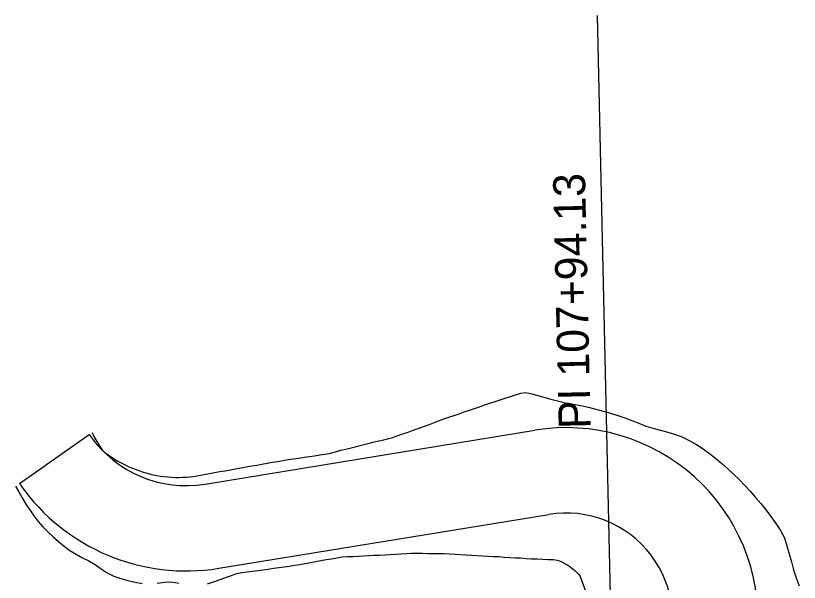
# Model space of a CAD drawing. Extents: x 834421 to 837111, y 495679 to 497078.
# Drawn here: x 835442.1 to 835588.9, y 496971.3 to 497077.5 of the extents above; entities that cross this region are included whole.
import ezdxf

# ---------------------------------------------------------------- set-up
doc = ezdxf.new("R2010")
doc.units = 0
for name, color, linetype in [('R_Horz Alg Annot', 7, 'Continuous'), ('R_Proposed Const Limits', 7, 'Continuous'), ('R_Proposed Road', 7, 'Continuous')]:
    doc.layers.add(name, color=color, linetype=linetype)

msp = doc.modelspace()

# ---------------------------------------------------------------- linework, layer by layer
at = {"layer": 'R_Horz Alg Annot'}
msp.add_lwpolyline([(835553.82, 496957.58), (835551.11, 497077.55)], dxfattribs=at)
at = {"layer": 'R_Proposed Const Limits'}
for points in [[(835458.28, 496996.14), (835458.82, 496995.66), (835459.42, 496995.22), (835460.02, 496994.81), (835460.63, 496994.41), (835461.25, 496994.04), (835461.89, 496993.69), (835462.52, 496993.36), (835463.17, 496993.04), (835463.82, 496992.75), (835464.48, 496992.49), (835465.15, 496992.24), (835465.82, 496992.02), (835466.5, 496991.81), (835467.17, 496991.63), (835467.86, 496991.47), (835468.54, 496991.33), (835469.23, 496991.22), (835469.91, 496991.12), (835470.6, 496991.05), (835471.29, 496991), (835471.98, 496990.98), (835472.67, 496990.97), (835473.35, 496990.99), (835474.03, 496991.02), (835474.71, 496991.08), (835475.39, 496991.17), (835476.06, 496991.27), (835476.72, 496991.39), (835477.41, 496991.54), (835478.4, 496991.71), (835479.38, 496991.89), (835480.37, 496992.06), (835481.35, 496992.23), (835482.34, 496992.4), (835483.32, 496992.59), (835484.3, 496992.78), (835485.29, 496992.95), (835486.27, 496993.12), (835487.26, 496993.29), (835488.24, 496993.46), (835489.23, 496993.63), (835490.21, 496993.8), (835491.2, 496993.97), (835492.18, 496994.14), (835493.17, 496994.3), (835494.16, 496994.45), (835495.15, 496994.59), (835496.14, 496994.74), (835497.13, 496994.89), (835498.12, 496995.03), (835499.11, 496995.18), (835500.1, 496995.33), (835501.08, 496995.52), (835502.05, 496995.79), (835503.02, 496996.05), (835503.99, 496996.29), (835504.97, 496996.53), (835505.94, 496996.77), (835506.91, 496997.02), (835507.89, 496997.26), (835508.86, 496997.5), (835509.83, 496997.74), (835510.81, 496997.98), (835511.78, 496998.23), (835512.76, 496998.47), (835513.71, 496998.8), (835514.67, 496999.14), (835515.63, 496999.48), (835516.59, 496999.81), (835517.55, 497000.15), (835518.5, 497000.49), (835519.46, 497000.83), (835520.41, 497001.21), (835521.36, 497001.6), (835522.32, 497001.97), (835523.28, 497002.29), (835524.24, 497002.6), (835525.2, 497002.92), (835526.16, 497003.25), (835527.12, 497003.57), (835528.08, 497003.9), (835529.04, 497004.23), (835530, 497004.55), (835530.96, 497004.88), (835531.92, 497005.21), (835532.88, 497005.53), (835533.84, 497005.85), (835534.8, 497006.16), (835535.76, 497006.47), (835536.73, 497006.79), (835537.72, 497006.89), (835539.04, 497006.58), (835540.62, 497006.17), (835542.16, 497005.73), (835543.66, 497005.34), (835545.13, 497004.97), (835546.57, 497004.72), (835548, 497004.44), (835549.41, 497004.13), (835550.81, 497003.79), (835552.19, 497003.42), (835553.56, 497003.02), (835554.91, 497002.59), (835556.24, 497002.13), (835557.56, 497001.64), (835558.87, 497001.13), (835560.16, 497000.58), (835561.52, 497000.18), (835562.91, 496999.82), (835564.31, 496999.43), (835565.71, 496998.99), (835567.12, 496998.52), (835568.41, 496997.84), (835569.68, 496997.11), (835570.93, 496996.33), (835572.11, 496995.45), (835573.27, 496994.54), (835574.4, 496993.59), (835575.51, 496992.61), (835576.6, 496991.6), (835577.68, 496990.55), (835578.72, 496989.48), (835579.75, 496988.37), (835580.75, 496987.22), (835581.74, 496986.05), (835582.7, 496984.85), (835583.63, 496983.61), (835584.54, 496982.34), (835585.43, 496981.03), (835586.14, 496979.64), (835586.62, 496978.16), (835587.07, 496976.66), (835587.47, 496975.16), (835587.83, 496973.64), (835588.37, 496972.16), (835588.94, 496970.66)], [(835456.41, 496999.4), (835456.77, 496998.66), (835457.11, 496998.02), (835457.47, 496997.38), (835457.86, 496996.75), (835458.28, 496996.14)], [(835442.1, 496989.32), (835442.67, 496988.25), (835443.33, 496987.11), (835444.01, 496985.98), (835444.74, 496984.87), (835445.51, 496983.78), (835446.33, 496982.72), (835447.22, 496981.72), (835448.15, 496980.76), (835449.12, 496979.83), (835450.13, 496978.93), (835451.17, 496978.06), (835452.27, 496977.29), (835453.42, 496976.58), (835454.6, 496975.92), (835455.8, 496975.3), (835456.98, 496974.64), (835458.11, 496973.84), (835459.27, 496973.07), (835460.51, 496972.45), (835461.81, 496972.03), (835463.14, 496971.66), (835464.47, 496971.34), (835465.82, 496971.07)], [(835478.06, 496971.03), (835479.37, 496971.47), (835480.62, 496971.92), (835481.58, 496972.26), (835482.54, 496972.6), (835483.49, 496972.93), (835484.48, 496973.13), (835485.47, 496973.26), (835486.46, 496973.39), (835487.45, 496973.53), (835488.44, 496973.66), (835489.43, 496973.79), (835490.42, 496973.93), (835491.42, 496974.06), (835492.41, 496974.19), (835493.4, 496974.33), (835494.38, 496974.5), (835495.37, 496974.67), (835496.35, 496974.85), (835497.34, 496975.02), (835498.32, 496975.2), (835499.31, 496975.38), (835500.29, 496975.55), (835501.28, 496975.73), (835502.26, 496975.9), (835503.25, 496976.07), (835504.25, 496976.12), (835505.26, 496976.17), (835506.26, 496976.22), (835507.27, 496976.27), (835508.27, 496976.32), (835509.28, 496976.37), (835510.28, 496976.42), (835511.29, 496976.47), (835512.29, 496976.52), (835513.3, 496976.57), (835514.3, 496976.62), (835515.3, 496976.69), (835516.3, 496976.77), (835517.32, 496976.76), (835518.33, 496976.75), (835519.35, 496976.73), (835520.37, 496976.72), (835521.38, 496976.7), (835522.4, 496976.69), (835523.41, 496976.67), (835524.44, 496976.6), (835525.46, 496976.54), (835526.48, 496976.48), (835527.51, 496976.42), (835528.53, 496976.35), (835529.56, 496976.29), (835530.58, 496976.23), (835531.6, 496976.17), (835532.63, 496976.11), (835533.65, 496976.04), (835534.67, 496975.98), (835535.7, 496975.92), (835536.72, 496975.86), (835537.74, 496975.79), (835538.77, 496975.73), (835539.79, 496975.69), (835540.81, 496975.64), (835541.83, 496975.6), (835542.85, 496975.56), (835543.59, 496975.46), (835544.01, 496975.3), (835544.42, 496975.13), (835544.81, 496974.94), (835545.2, 496974.73), (835545.56, 496974.51), (835545.91, 496974.28), (835546.24, 496974.04), (835546.56, 496973.78), (835546.86, 496973.52), (835547.14, 496973.25), (835547.41, 496972.97), (835547.66, 496972.68), (835547.9, 496972.37), (835549.85, 496966.91)], [(835468.6, 496971.11), (835469.98, 496971.31), (835471.33, 496971.39), (835472.66, 496971.17)]]:
    msp.add_lwpolyline(points, dxfattribs=at)
at = {"layer": 'R_Proposed Road'}
for p, q in [((835477.61, 496989.72), (835539.41, 496999.83)), ((835442.81, 496989.81), (835455.89, 496999.03)), ((835455.89, 496999.03), (835456.07, 496998.76)), ((835442.81, 496989.81), (835442.99, 496989.55)), ((835480.19, 496973.93), (835541.99, 496984.04))]:
    msp.add_line(p, q, dxfattribs=at)
for centre, radius, start, end in [((835545.22, 496964.3), 36, 357.0392, 99.2892), ((835474.06, 497011.43), 22, 215.165, 279.2892), ((835474.06, 497011.43), 38, 215.165, 279.2892), ((835545.22, 496964.3), 20, 272.9479, 99.2892)]:
    msp.add_arc(centre, radius, start, end, dxfattribs=at)

# ---------------------------------------------------------------- texts
at = {"layer": 'R_Horz Alg Annot'}
msp.add_text('PI 107+94.13', height=6, rotation=91.2958, dxfattribs=at).set_placement((835549.86, 497000.13))

doc.saveas('drawing.dxf')
